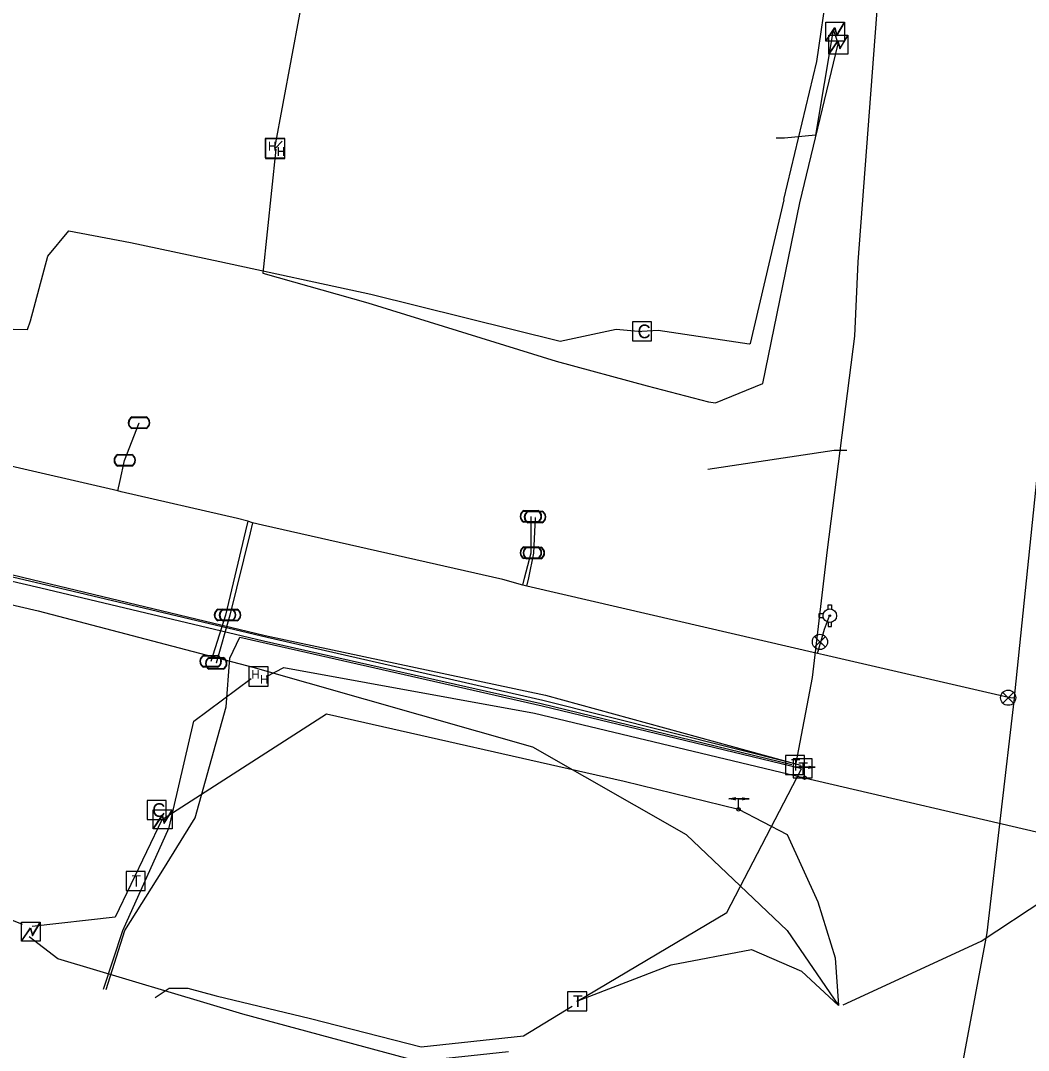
# Model space of a CAD drawing. Extents: x 2070721 to 2083340, y 729290 to 737883.
# Drawn here: x 2082067.6 to 2082363.4, y 736186.8 to 736489 of the extents above; entities that cross this region are included whole.
import ezdxf

# ---------------------------------------------------------------- set-up
doc = ezdxf.new("R2010")
doc.units = 0
for name, color, linetype in [('Exist Utilities Power Change of Service SUE CELL', 7, 'Continuous'), ('Exist Utilities Power Hand Hole CELL', 7, 'Continuous'), ('Exist Utilities Power Transformer CELL', 7, 'Continuous'), ('Exist Utilities Power UG Cable SUE LOS B', 7, 'Continuous'), ('Exist Utilities Power UG Cable SUE LOS C', 7, 'Continuous'), ('Exist Utilities Telephone Change of Service SUE CELL', 7, 'Continuous'), ('Exist Utilities Telephone Hand Hole CELL', 7, 'Continuous'), ('Exist Utilities Telephone Pedestal CELL', 7, 'Continuous'), ('Exist Utilities Telephone UG Cable SUE LOS C', 7, 'Continuous'), ('Exist Utilities Telephone UG FO SUE LOS B', 7, 'Continuous'), ('Exist Utilities Telephone UG FO SUE LOS C', 7, 'Continuous'), ('Exist Utilities TV Pedestal CELL', 7, 'Continuous'), ('Exist Utilities TV UG Cable SUE LOS C', 7, 'Continuous'), ('Exist Utilities Water Fire Hydrant CELL', 7, 'Continuous'), ('Exist Utilities Water Meter CELL', 7, 'Continuous'), ('Exist Utilities Water UG Line SUE LOS B', 7, 'Continuous'), ('Exist Utilities Water Valve CELL', 7, 'Continuous')]:
    doc.layers.add(name, color=color, linetype=linetype)

msp = doc.modelspace()

# ---------------------------------------------------------------- linework, layer by layer
at = {"layer": 'Exist Utilities Power Change of Service SUE CELL'}
for p, q in [((2082281.41, 736260.62), (2082275.44, 736260.62)), ((2082278.27, 736257.54), (2082278.27, 736260.62)), ((2082278.27, 736260.62), (2082281.41, 736260.62)), ((2082278.27, 736257.54), (2082278.27, 736257.54))]:
    msp.add_line(p, q, dxfattribs=at)
for points in [[(2082275.44, 736260.62), (2082277.41, 736260.97), (2082276.99, 736260.62), (2082277.38, 736260.32)], [(2082281.41, 736260.62), (2082279.43, 736260.28), (2082279.85, 736260.62), (2082279.47, 736260.93)]]:
    msp.add_lwpolyline(points, close=True, dxfattribs=at)
msp.add_circle((2082278.27, 736257.54), 0.517, dxfattribs=at)
at = {"layer": 'Exist Utilities Power Hand Hole CELL'}
for p, q in [((2082142.36, 736451.38), (2082142.36, 736451.38)), ((2082142.38, 736451.24), (2082142.38, 736451.24))]:
    msp.add_line(p, q, dxfattribs=at)
for points in [[(2082139.41, 736448.66), (2082145.16, 736448.66), (2082145.16, 736454.41), (2082139.41, 736454.41), (2082139.41, 736448.66)], [(2082139.43, 736448.52), (2082145.18, 736448.52), (2082145.18, 736454.27), (2082139.43, 736454.27), (2082139.43, 736448.52)]]:
    msp.add_lwpolyline(points, dxfattribs=at)
at = {"layer": 'Exist Utilities Power Transformer CELL'}
for p, q in [((2082306.73, 736485.89), (2082306.73, 736485.89)), ((2082307.68, 736482.03), (2082307.68, 736482.03)), ((2082109.36, 736254.78), (2082109.36, 736254.78)), ((2082070.65, 736221.81), (2082070.65, 736221.81))]:
    msp.add_line(p, q, dxfattribs=at)
for points in [[(2082303.88, 736488.5), (2082309.44, 736488.5), (2082309.44, 736482.95), (2082303.88, 736482.95)], [(2082304.84, 736484.64), (2082310.39, 736484.64), (2082310.39, 736479.09), (2082304.84, 736479.09)], [(2082106.52, 736257.39), (2082112.07, 736257.39), (2082112.07, 736251.84), (2082106.52, 736251.84)], [(2082067.81, 736224.42), (2082073.36, 736224.42), (2082073.36, 736218.87), (2082067.81, 736218.87)]]:
    msp.add_lwpolyline(points, close=True, dxfattribs=at)
for points in [[(2082303.88, 736482.95), (2082306.53, 736486.89), (2082307.16, 736484.68), (2082309.44, 736488.5)], [(2082303.95, 736482.95), (2082306.53, 736486.68), (2082307.11, 736484.5), (2082309.44, 736488.34)], [(2082304.84, 736479.09), (2082307.48, 736483.03), (2082308.11, 736480.82), (2082310.39, 736484.64)], [(2082304.91, 736479.09), (2082307.48, 736482.82), (2082308.07, 736480.64), (2082310.39, 736484.49)], [(2082106.52, 736251.84), (2082109.16, 736255.78), (2082109.79, 736253.57), (2082112.07, 736257.39)], [(2082106.59, 736251.84), (2082109.16, 736255.57), (2082109.75, 736253.39), (2082112.07, 736257.24)], [(2082067.81, 736218.87), (2082070.45, 736222.81), (2082071.08, 736220.6), (2082073.36, 736224.42)], [(2082067.88, 736218.87), (2082070.45, 736222.6), (2082071.04, 736220.42), (2082073.36, 736224.27)]]:
    msp.add_lwpolyline(points, dxfattribs=at)
at = {"layer": 'Exist Utilities Power UG Cable SUE LOS B'}
for p, q in [((2082307.68, 736482.03), (2082306.13, 736486.24)), ((2082142.32, 736451.4), (2082144.32, 736453.59))]:
    msp.add_line(p, q, dxfattribs=at)
for points in [[(2082142.24, 736451.57), (2082149.5, 736490.83), (2082151.41, 736499.09)], [(2082305.96, 736485.62), (2082300.89, 736455.33), (2082291.77, 736454.45), (2082289.34, 736454.45)], [(2082271.53, 736376.84), (2082285.41, 736382.49), (2082296.3, 736435.5), (2082307.51, 736482.11)], [(2082142.46, 736451.19), (2082138.63, 736414.9), (2082169.51, 736406.15), (2082224.78, 736389.04), (2082251.44, 736381.79), (2082269.44, 736377.14), (2082271.53, 736376.84)], [(2082269.25, 736357.35), (2082306.32, 736362.94), (2082308.86, 736362.94), (2082310.07, 736362.94)], [(2082109.4, 736254.71), (2082157.41, 736285.53), (2082244.68, 736265.83), (2082278.27, 736257.54)], [(2082008.8, 736279.06), (2082001.18, 736250.65), (2082068.04, 736223.8)], [(2082109.16, 736254.62), (2082095.38, 736225.9), (2082070.95, 736223.19)], [(2082210.82, 736186.38), (2082184.27, 736183.56), (2082132.77, 736197.39), (2082078.53, 736213.65), (2082070.12, 736220.15)]]:
    msp.add_lwpolyline(points, dxfattribs=at)
at = {"layer": 'Exist Utilities Power UG Cable SUE LOS C'}
msp.add_lwpolyline([(2082278.27, 736257.54), (2082292.55, 736250.13), (2082301.58, 736230.36), (2082306.66, 736213.99), (2082307.6, 736199.94)], dxfattribs=at)
at = {"layer": 'Exist Utilities Telephone Change of Service SUE CELL'}
for p, q in [((2082300.82, 736269.89), (2082294.85, 736269.89)), ((2082297.68, 736266.81), (2082297.68, 736269.89)), ((2082297.68, 736269.89), (2082300.82, 736269.89)), ((2082297.68, 736266.81), (2082297.68, 736266.81))]:
    msp.add_line(p, q, dxfattribs=at)
for points in [[(2082294.85, 736269.89), (2082296.82, 736270.24), (2082296.4, 736269.89), (2082296.79, 736269.59)], [(2082300.82, 736269.89), (2082298.84, 736269.55), (2082299.26, 736269.89), (2082298.88, 736270.2)]]:
    msp.add_lwpolyline(points, close=True, dxfattribs=at)
msp.add_circle((2082297.68, 736266.81), 0.517, dxfattribs=at)
at = {"layer": 'Exist Utilities Telephone Hand Hole CELL'}
for p, q in [((2082134.54, 736299.36), (2082134.54, 736293.64)), ((2082140.26, 736299.36), (2082134.54, 736299.36)), ((2082140.26, 736293.64), (2082140.26, 736299.36)), ((2082134.54, 736293.64), (2082140.26, 736293.64)), ((2082137.4, 736296.5), (2082137.4, 736296.5))]:
    msp.add_line(p, q, dxfattribs=at)
at = {"layer": 'Exist Utilities Telephone Pedestal CELL'}
for p, q in [((2082294.79, 736270.59), (2082294.79, 736270.59)), ((2082297.01, 736269.62), (2082297.01, 736269.62)), ((2082101.28, 736236.51), (2082101.28, 736236.51)), ((2082230.86, 736201.26), (2082230.86, 736201.26))]:
    msp.add_line(p, q, dxfattribs=at)
for points in [[(2082292.07, 736267.76), (2082297.66, 736267.76), (2082297.66, 736273.36), (2082292.07, 736273.36), (2082292.07, 736267.76)], [(2082294.29, 736266.79), (2082299.88, 736266.79), (2082299.88, 736272.39), (2082294.29, 736272.39), (2082294.29, 736266.79)], [(2082098.56, 736233.68), (2082104.15, 736233.68), (2082104.15, 736239.28), (2082098.56, 736239.28), (2082098.56, 736233.68)], [(2082228.14, 736198.43), (2082233.73, 736198.43), (2082233.73, 736204.03), (2082228.14, 736204.03), (2082228.14, 736198.43)]]:
    msp.add_lwpolyline(points, dxfattribs=at)
at = {"layer": 'Exist Utilities Telephone UG Cable SUE LOS C'}
for points in [[(2082313.36, 736418.13), (2082323.5, 736551.56), (2082325.19, 736575.84), (2082324.51, 736589.38), (2082321.65, 736591.13), (2082314.03, 736592.42), (2082290.9, 736590.33)], [(2081568.17, 736468.83), (2081615.92, 736445.96), (2081696.31, 736415.49), (2081804.57, 736385.24), (2081915.03, 736359.08), (2081987.17, 736342.62), (2082073.48, 736322.55), (2082138.89, 736307.01), (2082220.41, 736288.62), (2082293.92, 736270.7)], [(2081568.48, 736469.51), (2081618.39, 736447.85), (2081696.88, 736418.07), (2081805.87, 736388.07), (2081916.17, 736362.01), (2081987.94, 736345.05), (2082073.78, 736324.33), (2082139.32, 736308.59), (2082221.63, 736291.02), (2082296.5, 736270.5)], [(2081615.72, 736447.72), (2081617.75, 736446.75), (2081696.77, 736417.12), (2081805.08, 736386.54), (2081915.58, 736360.92), (2081915.48, 736360.89), (2081987.51, 736343.92), (2082073.49, 736323.81), (2082139.92, 736308.03), (2082220.81, 736289.54), (2082294.45, 736271.08)], [(2082295.23, 736271.11), (2082300.01, 736296.17), (2082304.41, 736333.72), (2082312.38, 736396.33), (2082313.36, 736418.13)], [(2082092.68, 736204.69), (2082098.21, 736221.96), (2082109.36, 736239.64), (2082118.86, 736255.05), (2082127.88, 736287.62), (2082128.99, 736301.9), (2082131.92, 736308.02), (2082137.48, 736306.8), (2082220.68, 736287.9), (2082296.51, 736269.59)], [(2082230.87, 736201.17), (2082274.89, 736227.31), (2082296.74, 736269.44)], [(2082309.03, 736200.13), (2082349.47, 736218.89), (2082368.17, 736231.22), (2082370.24, 736249.61), (2082392.9, 736262.1)], [(2082230.86, 736201.26), (2082258.55, 736211.96), (2082282.14, 736216.42), (2082296.8, 736210.02), (2082307.6, 736199.94)], [(2082107.12, 736202.32), (2082111.17, 736205.08), (2082116.7, 736205.08), (2082124.99, 736202.78), (2082152.65, 736196.19), (2082185.11, 736187.86), (2082215.2, 736191.06), (2082229.49, 736199.82)]]:
    msp.add_lwpolyline(points, dxfattribs=at)
at = {"layer": 'Exist Utilities Telephone UG FO SUE LOS B'}
for points in [[(2082139.75, 736296.47), (2082144.85, 736299.13), (2082218.4, 736285.8), (2082297.68, 736266.81)], [(2082091.94, 736204.81), (2082097.62, 736222.03), (2082111.17, 736252.22), (2082118.46, 736283.41), (2082135.22, 736295.91)]]:
    msp.add_lwpolyline(points, dxfattribs=at)
at = {"layer": 'Exist Utilities Telephone UG FO SUE LOS C'}
msp.add_line((2082297.68, 736266.81), (2082369.98, 736249.96), dxfattribs=at)
at = {"layer": 'Exist Utilities TV Pedestal CELL'}
for p, q in [((2082249.96, 736397.77), (2082249.96, 736397.77)), ((2082107.52, 736257.33), (2082107.52, 736257.33))]:
    msp.add_line(p, q, dxfattribs=at)
for points in [[(2082247.18, 736394.99), (2082252.73, 736394.99), (2082252.73, 736400.54), (2082247.18, 736400.54), (2082247.18, 736394.99)], [(2082104.75, 736254.56), (2082110.3, 736254.56), (2082110.3, 736260.1), (2082104.75, 736260.1), (2082104.75, 736254.56)]]:
    msp.add_lwpolyline(points, dxfattribs=at)
at = {"layer": 'Exist Utilities TV UG Cable SUE LOS C'}
msp.add_line((2082281.76, 736394.25), (2082291.67, 736436.35), dxfattribs=at)
for points in [[(2082291.62, 736436.42), (2082301.26, 736476.92), (2082307.72, 736521.26), (2082314.13, 736551.45), (2082318.86, 736581.32), (2082318.86, 736581.32)], [(2081867.92, 736374.85), (2081908.54, 736402.92), (2081922.2, 736410.85), (2081955.72, 736410.85), (2081976.56, 736410.85), (2082011.49, 736410.85), (2082028.68, 736408.17), (2082065.29, 736398.47), (2082069.56, 736398.28), (2082070.52, 736400.88), (2082075.6, 736419.83), (2082081.77, 736427.24), (2082099.8, 736423.88), (2082126.06, 736418.32), (2082170.39, 736408.66), (2082225.96, 736394.95), (2082242.36, 736398.41), (2082249.96, 736397.77)], [(2082281.76, 736394.25), (2082281.45, 736394.01), (2082254.75, 736398.03), (2082249.96, 736397.77)], [(2081867.92, 736374.85), (2081869.92, 736367.25), (2081876.67, 736362.95), (2081888.78, 736359.07), (2081912.22, 736353.44), (2081986.37, 736335.81), (2082072.78, 736315.77), (2082135.75, 736299.21), (2082217.86, 736275.92), (2082262.9, 736250.17), (2082262.99, 736250.08), (2082292.59, 736221.95), (2082307.6, 736199.94)]]:
    msp.add_lwpolyline(points, dxfattribs=at)
at = {"layer": 'Exist Utilities Water Fire Hydrant CELL'}
msp.add_line((2082305.08, 736314.34), (2082305.08, 736314.34), dxfattribs=at)
for points in [[(2082303.17, 736314.85), (2082301.88, 736314.85), (2082301.88, 736313.83), (2082303.17, 736313.83)], [(2082304.57, 736316.25), (2082304.57, 736317.54), (2082305.59, 736317.54), (2082305.59, 736316.23)], [(2082304.57, 736312.43), (2082304.57, 736311.14), (2082305.59, 736311.14), (2082305.59, 736312.45)]]:
    msp.add_lwpolyline(points, dxfattribs=at)
for radius in [1.98, 0.243]:
    msp.add_circle((2082305.08, 736314.34), radius, dxfattribs=at)
at = {"layer": 'Exist Utilities Water Meter CELL'}
for p, q in [((2082102.36, 736370.96), (2082102.36, 736370.96)), ((2082098.17, 736359.95), (2082098.17, 736359.95)), ((2082217.35, 736343.5), (2082217.35, 736343.5)), ((2082218.59, 736343.33), (2082218.59, 736343.33)), ((2082217.36, 736332.83), (2082217.36, 736332.83)), ((2082218.23, 736332.76), (2082218.23, 736332.76)), ((2082127.6, 736314.6), (2082127.6, 736314.6)), ((2082129.07, 736314.52), (2082129.07, 736314.52)), ((2082123.36, 736300.98), (2082123.36, 736300.98)), ((2082125, 736300.36), (2082125, 736300.36))]:
    msp.add_line(p, q, dxfattribs=at)
for points in [[(2082100.32, 736372.66), (2082104.4, 736372.66)], [(2082100.32, 736372.52), (2082104.4, 736372.52)], [(2082104.4, 736369.4), (2082100.3, 736369.4)], [(2082104.4, 736369.26), (2082100.3, 736369.26)], [(2082096.13, 736361.65), (2082100.21, 736361.65)], [(2082096.13, 736361.51), (2082100.21, 736361.51)], [(2082100.21, 736358.39), (2082096.11, 736358.39)], [(2082100.21, 736358.25), (2082096.11, 736358.25)], [(2082215.31, 736345.2), (2082219.39, 736345.2)], [(2082215.31, 736345.06), (2082219.39, 736345.06)], [(2082216.55, 736345.03), (2082220.63, 736345.03)], [(2082219.39, 736341.94), (2082215.29, 736341.94)], [(2082216.55, 736344.89), (2082220.63, 736344.89)], [(2082219.39, 736341.8), (2082215.29, 736341.8)], [(2082220.63, 736341.77), (2082216.53, 736341.77)], [(2082220.63, 736341.63), (2082216.53, 736341.63)], [(2082215.32, 736334.53), (2082219.4, 736334.53)], [(2082215.32, 736334.39), (2082219.4, 736334.39)], [(2082216.19, 736334.46), (2082220.27, 736334.46)], [(2082216.19, 736334.32), (2082220.27, 736334.32)], [(2082219.4, 736331.27), (2082215.3, 736331.27)], [(2082219.4, 736331.13), (2082215.3, 736331.13)], [(2082220.27, 736331.2), (2082216.17, 736331.2)], [(2082220.27, 736331.06), (2082216.17, 736331.06)], [(2082125.56, 736316.3), (2082129.64, 736316.3)], [(2082125.56, 736316.16), (2082129.64, 736316.16)], [(2082127.03, 736316.22), (2082131.11, 736316.22)], [(2082127.03, 736316.08), (2082131.11, 736316.08)], [(2082129.64, 736313.04), (2082125.54, 736313.04)], [(2082129.64, 736312.9), (2082125.54, 736312.9)], [(2082131.11, 736312.96), (2082127.01, 736312.96)], [(2082131.11, 736312.82), (2082127.01, 736312.82)], [(2082121.32, 736302.68), (2082125.4, 736302.68)], [(2082121.32, 736302.54), (2082125.4, 736302.54)], [(2082122.96, 736302.06), (2082127.04, 736302.06)], [(2082122.96, 736301.92), (2082127.04, 736301.92)], [(2082125.4, 736299.42), (2082121.3, 736299.42)], [(2082125.4, 736299.28), (2082121.3, 736299.28)], [(2082127.04, 736298.8), (2082122.94, 736298.8)], [(2082127.04, 736298.66), (2082122.94, 736298.66)]]:
    msp.add_lwpolyline(points, dxfattribs=at)
for centre, radius, start, end in [((2082101.05, 736370.95), 1.86, 113.178, 245.9794), ((2082101.06, 736370.95), 1.73, 115.3009, 243.7824), ((2082103.65, 736370.96), 1.86, 293.6483, 66.3084), ((2082103.66, 736370.96), 1.73, 295.1272, 64.8728), ((2082096.86, 736359.94), 1.86, 113.178, 245.9794), ((2082096.87, 736359.94), 1.73, 115.3009, 243.7824), ((2082099.46, 736359.95), 1.86, 293.6483, 66.3084), ((2082099.47, 736359.95), 1.73, 295.1272, 64.8728), ((2082216.04, 736343.49), 1.86, 113.178, 245.9794), ((2082216.05, 736343.49), 1.73, 115.3009, 243.7824), ((2082217.28, 736343.32), 1.86, 113.178, 245.9794), ((2082218.64, 736343.5), 1.86, 293.6483, 66.3084), ((2082218.65, 736343.5), 1.73, 295.1272, 64.8728), ((2082219.88, 736343.33), 1.86, 293.6483, 66.3084), ((2082217.29, 736343.32), 1.73, 115.3009, 243.7824), ((2082219.89, 736343.33), 1.73, 295.1272, 64.8728), ((2082216.05, 736332.82), 1.86, 113.178, 245.9794), ((2082216.06, 736332.82), 1.73, 115.3009, 243.7824), ((2082216.92, 736332.75), 1.86, 113.178, 245.9794), ((2082216.93, 736332.75), 1.73, 115.3009, 243.7824), ((2082218.65, 736332.83), 1.86, 293.6483, 66.3084), ((2082218.66, 736332.83), 1.73, 295.1272, 64.8728), ((2082219.52, 736332.76), 1.86, 293.6483, 66.3084), ((2082219.53, 736332.76), 1.73, 295.1272, 64.8728), ((2082126.29, 736314.59), 1.86, 113.178, 245.9794), ((2082126.3, 736314.59), 1.73, 115.3009, 243.7824), ((2082127.76, 736314.51), 1.86, 113.178, 245.9794), ((2082127.77, 736314.51), 1.73, 115.3009, 243.7824), ((2082128.89, 736314.6), 1.86, 293.6483, 66.3084), ((2082128.9, 736314.6), 1.73, 295.1272, 64.8728), ((2082130.36, 736314.52), 1.86, 293.6483, 66.3084), ((2082130.37, 736314.52), 1.73, 295.1272, 64.8728), ((2082122.05, 736300.97), 1.86, 113.178, 245.9794), ((2082124.65, 736300.98), 1.86, 293.6483, 66.3084), ((2082122.06, 736300.97), 1.73, 115.3009, 243.7824), ((2082123.69, 736300.35), 1.86, 113.178, 245.9794), ((2082123.7, 736300.35), 1.73, 115.3009, 243.7824), ((2082124.66, 736300.98), 1.73, 295.1272, 64.8728), ((2082126.29, 736300.36), 1.86, 293.6483, 66.3084), ((2082126.3, 736300.36), 1.73, 295.1272, 64.8728)]:
    msp.add_arc(centre, radius, start, end, dxfattribs=at)
at = {"layer": 'Exist Utilities Water UG Line SUE LOS B'}
for points in [[(2082359.3, 736290.13), (2082359.45, 736292.32), (2082374.67, 736439.46), (2082381.09, 736508.57), (2082384.35, 736558.86)], [(2082096.13, 736351.01), (2082096.83, 736353.98), (2082098.08, 736359.89), (2082102.34, 736370.98)], [(2082096.13, 736351.01), (2082024.3, 736367.53)], [(2082131.26, 736342.83), (2082097.1, 736350.7), (2082096.13, 736351.01)], [(2082134.24, 736342.06), (2082133.57, 736339.25), (2082127.69, 736314.54), (2082123.39, 736300.94)], [(2082135.62, 736341.57), (2082134.24, 736342.06), (2082131.26, 736342.83)], [(2082214.95, 736323.31), (2082215.49, 736325.35), (2082217.47, 736332.78), (2082217.41, 736343.47)], [(2082216.16, 736323.06), (2082216.72, 736325.51), (2082218.24, 736332.74), (2082218.7, 736343.21)], [(2082135.62, 736341.57), (2082134.96, 736338.69), (2082129.02, 736314.54), (2082124.97, 736300.43)], [(2082214.95, 736323.31), (2082209.11, 736324.97), (2082138.6, 736340.96), (2082135.62, 736341.57)], [(2082216.16, 736323.06), (2082214.95, 736323.31)], [(2082301.46, 736303.24), (2082226.74, 736320.57), (2082216.16, 736323.06)], [(2082301.46, 736303.24), (2082303.57, 736310.44), (2082305, 736314.34)], [(2082359.3, 736290.13), (2082358.07, 736290.29), (2082357.52, 736290.36), (2082303.24, 736302.85), (2082301.46, 736303.24)], [(2082320.68, 735936.86), (2082316.05, 736027.92), (2082334.72, 736133.01), (2082351.23, 736221.26), (2082359.3, 736290.13)]]:
    msp.add_lwpolyline(points, dxfattribs=at)
at = {"layer": 'Exist Utilities Water Valve CELL'}
for points in [[(2082303.77, 736308.23), (2082300.61, 736305.08), (2082302.19, 736306.66), (2082303.77, 736305.08), (2082300.61, 736308.23)], [(2082359.02, 736291.86), (2082355.86, 736288.71), (2082357.44, 736290.29), (2082359.02, 736288.71), (2082355.86, 736291.86)]]:
    msp.add_lwpolyline(points, dxfattribs=at)
for centre in [(2082302.19, 736306.66), (2082357.44, 736290.29)]:
    msp.add_circle(centre, 2.23, dxfattribs=at)

# ---------------------------------------------------------------- texts
at = {"layer": 'Exist Utilities Power Hand Hole CELL'}
for p in [(2082140.2, 736450.91), (2082140.22, 736450.77), (2082142.77, 736449.39), (2082142.79, 736449.25)]:
    msp.add_text('H', height=2.5, dxfattribs=at).set_placement(p)
at = {"layer": 'Exist Utilities Telephone Hand Hole CELL'}
for p in [(2082135.32, 736295.91), (2082137.89, 736294.44)]:
    msp.add_text('H', height=2.5, dxfattribs=at).set_placement(p)
at = {"layer": 'Exist Utilities Telephone Pedestal CELL'}
for p in [(2082293.66, 736268.88), (2082295.88, 736267.91), (2082100.15, 736234.8), (2082229.73, 736199.55)]:
    msp.add_text('T', height=3.42, dxfattribs=at).set_placement(p)
at = {"layer": 'Exist Utilities TV Pedestal CELL'}
for p in [(2082248.65, 736395.77), (2082106.21, 736255.33)]:
    msp.add_text('C', height=4, dxfattribs=at).set_placement(p)

doc.saveas('drawing.dxf')
